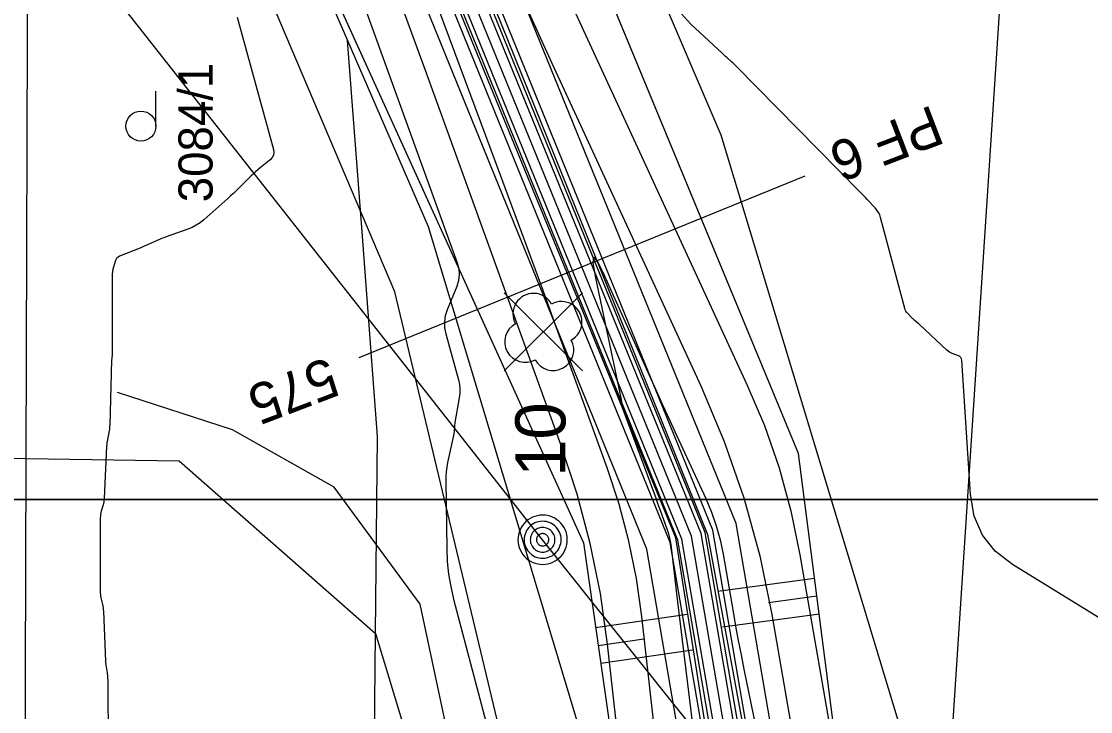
# Model space of a CAD drawing. Extents: x -534410 to -534262, y -1190162 to -1189584.
# Drawn here: x -534342.11 to -534315.47, y -1190009.76 to -1189992.55 of the extents above; entities that cross this region are included whole.
import ezdxf

# ---------------------------------------------------------------- set-up
doc = ezdxf.new("R2010")
doc.units = 0
for name, color, linetype in [('07_ELEKTRO', 7, 'Continuous'), ('30', 7, 'Continuous'), ('31', 7, 'Continuous'), ('_linie', 7, 'Continuous'), ('_N_osa', 7, 'Continuous'), ('_N_tenká', 7, 'Continuous'), ('_N_tenká_velmi', 7, 'Continuous'), ('_N_text', 7, 'Continuous'), ('_přístup', 7, 'Continuous'), ('_rámeček', 7, 'Continuous'), ('_tenka', 7, 'Continuous'), ('_velmi_tenka', 7, 'Continuous'), ('Default', 7, 'Continuous'), ('Hranice parcel', 7, 'Continuous'), ('Parcelní čísla', 7, 'Continuous'), ('Vrstva 12', 7, 'Continuous'), ('Vrstva 15', 7, 'Continuous'), ('Vrstva 2', 7, 'Continuous'), ('Značky kultur', 7, 'Continuous')]:
    doc.layers.add(name, color=color, linetype=linetype)

# ---------------------------------------------------------------- blocks, each defined once
blk = doc.blocks.new('VN460')
at = {"layer": 'Vrstva 2'}
for points in [[(0.1229, -0.0001), (0.1221, 0.0128), (0.1201, 0.0255), (0.1168, 0.0379), (0.1122, 0.0499), (0.1064, 0.0613), (0.0994, 0.0722), (0.0913, 0.0822), (0.0822, 0.0912), (0.0722, 0.0993), (0.0614, 0.1063), (0.05, 0.1122), (0.0379, 0.1168), (0.0256, 0.1201), (0.0128, 0.1221), (0, 0.1228), (-0.0128, 0.1221), (-0.0256, 0.1201), (-0.0379, 0.1168), (-0.05, 0.1122), (-0.0614, 0.1063), (-0.0722, 0.0993), (-0.0822, 0.0912), (-0.0913, 0.0822), (-0.0994, 0.0722), (-0.1064, 0.0613), (-0.1122, 0.0499), (-0.1168, 0.0379), (-0.1202, 0.0255), (-0.1221, 0.0128), (-0.1229, -0.0001), (-0.1221, -0.0129), (-0.1202, -0.0256), (-0.1168, -0.038), (-0.1122, -0.05), (-0.1064, -0.0615), (-0.0994, -0.0723), (-0.0913, -0.0823), (-0.0822, -0.0914), (-0.0722, -0.0995), (-0.0614, -0.1064), (-0.05, -0.1123), (-0.0379, -0.1169), (-0.0256, -0.1202), (-0.0128, -0.1223), (0, -0.1229), (0.0128, -0.1222), (0.0256, -0.1202), (0.0379, -0.1169), (0.05, -0.1123), (0.0614, -0.1064), (0.0722, -0.0995), (0.0822, -0.0914), (0.0913, -0.0823), (0.0994, -0.0723), (0.1064, -0.0615), (0.1122, -0.05), (0.1168, -0.038), (0.1201, -0.0256), (0.1221, -0.0129), (0.1229, -0.0001)], [(0.0922, -0.0001), (0.0916, 0.0096), (0.0901, 0.0191), (0.0876, 0.0284), (0.0842, 0.0374), (0.0798, 0.046), (0.0745, 0.0541), (0.0685, 0.0616), (0.0616, 0.0684), (0.0541, 0.0745), (0.046, 0.0797), (0.0375, 0.0841), (0.0285, 0.0876), (0.0191, 0.0901), (0.0096, 0.0916), (0, 0.0921), (-0.0096, 0.0916), (-0.0191, 0.0901), (-0.0285, 0.0876), (-0.0375, 0.0841), (-0.0461, 0.0797), (-0.0542, 0.0745), (-0.0617, 0.0684), (-0.0685, 0.0616), (-0.0745, 0.0541), (-0.0798, 0.046), (-0.0842, 0.0374), (-0.0876, 0.0284), (-0.0901, 0.0191), (-0.0916, 0.0096), (-0.0921, -0.0001), (-0.0916, -0.0097), (-0.0901, -0.0192), (-0.0876, -0.0285), (-0.0842, -0.0375), (-0.0798, -0.0461), (-0.0745, -0.0542), (-0.0685, -0.0617), (-0.0616, -0.0685), (-0.0542, -0.0746), (-0.0461, -0.0798), (-0.0375, -0.0842), (-0.0285, -0.0877), (-0.0191, -0.0902), (-0.0096, -0.0917), (0, -0.0922), (0.0096, -0.0917), (0.0191, -0.0902), (0.0285, -0.0877), (0.0375, -0.0842), (0.046, -0.0798), (0.0541, -0.0746), (0.0616, -0.0685), (0.0685, -0.0617), (0.0745, -0.0542), (0.0798, -0.0461), (0.0842, -0.0375), (0.0876, -0.0285), (0.0901, -0.0192), (0.0916, -0.0097), (0.0922, -0.0001)], [(0.0614, -0.0001), (0.0611, 0.0063), (0.0601, 0.0127), (0.0584, 0.0189), (0.0561, 0.0249), (0.0532, 0.0306), (0.0497, 0.036), (0.0456, 0.041), (0.0411, 0.0456), (0.0361, 0.0496), (0.0307, 0.0531), (0.025, 0.056), (0.019, 0.0584), (0.0128, 0.06), (0.0064, 0.061), (0, 0.0613), (-0.0064, 0.061), (-0.0128, 0.06), (-0.019, 0.0584), (-0.025, 0.056), (-0.0307, 0.0531), (-0.0361, 0.0496), (-0.0411, 0.0456), (-0.0457, 0.041), (-0.0497, 0.036), (-0.0532, 0.0306), (-0.0561, 0.0249), (-0.0584, 0.0189), (-0.0601, 0.0127), (-0.0611, 0.0063), (-0.0614, -0.0001), (-0.0611, -0.0065), (-0.0601, -0.0128), (-0.0584, -0.0191), (-0.0561, -0.025), (-0.0532, -0.0308), (-0.0497, -0.0361), (-0.0457, -0.0411), (-0.0411, -0.0457), (-0.0361, -0.0498), (-0.0307, -0.0532), (-0.025, -0.0561), (-0.019, -0.0585), (-0.0128, -0.0601), (-0.0064, -0.0611), (0, -0.0615), (0.0064, -0.0611), (0.0128, -0.0601), (0.019, -0.0585), (0.025, -0.0561), (0.0307, -0.0532), (0.0361, -0.0498), (0.0411, -0.0457), (0.0456, -0.0411), (0.0497, -0.0361), (0.0532, -0.0308), (0.0561, -0.025), (0.0584, -0.0191), (0.0601, -0.0128), (0.0611, -0.0065), (0.0614, -0.0001)], [(0.0307, -0.0001), (0.0306, 0.0031), (0.03, 0.0063), (0.0292, 0.0094), (0.0281, 0.0124), (0.0266, 0.0153), (0.0248, 0.018), (0.0228, 0.0205), (0.0206, 0.0228), (0.0181, 0.0248), (0.0153, 0.0265), (0.0125, 0.028), (0.0095, 0.0291), (0.0064, 0.03), (0.0032, 0.0305), (0, 0.0306), (-0.0032, 0.0305), (-0.0064, 0.03), (-0.0095, 0.0291), (-0.0125, 0.028), (-0.0154, 0.0265), (-0.0181, 0.0248), (-0.0206, 0.0228), (-0.0228, 0.0205), (-0.0248, 0.018), (-0.0266, 0.0153), (-0.0281, 0.0124), (-0.0292, 0.0094), (-0.03, 0.0063), (-0.0306, 0.0031), (-0.0307, -0.0001), (-0.0306, -0.0033), (-0.03, -0.0065), (-0.0292, -0.0095), (-0.0281, -0.0126), (-0.0266, -0.0154), (-0.0248, -0.0181), (-0.0228, -0.0206), (-0.0206, -0.0229), (-0.0181, -0.0249), (-0.0154, -0.0267), (-0.0125, -0.0281), (-0.0095, -0.0292), (-0.0064, -0.0301), (-0.0032, -0.0306), (0, -0.0308), (0.0032, -0.0306), (0.0064, -0.0301), (0.0095, -0.0292), (0.0125, -0.0281), (0.0153, -0.0267), (0.0181, -0.0249), (0.0206, -0.0229), (0.0228, -0.0206), (0.0248, -0.0181), (0.0266, -0.0154), (0.0281, -0.0126), (0.0292, -0.0095), (0.03, -0.0065), (0.0306, -0.0033), (0.0307, -0.0001)]]:
    blk.add_lwpolyline(points, dxfattribs=at)

msp = doc.modelspace()

# ---------------------------------------------------------------- linework, layer by layer
at = {"layer": '07_ELEKTRO'}
msp.add_lwpolyline([(-534329.31, -1190087.46), (-534329.03, -1190079.95), (-534329.01, -1190078.66), (-534328.95, -1190069.47), (-534328.91, -1190061.75), (-534328.68, -1190054.09), (-534328.55, -1190046.44), (-534328.261, -1190025.497), (-534332.174, -1190007.081), (-534334.321, -1190004.167), (-534336.852, -1190002.737), (-534339.713, -1190001.803)], dxfattribs=at)
at = {"layer": '30'}
for points in [[(-534330.583, -1189987.403), (-534324.037, -1190001.603), (-534323.602, -1190002.632), (-534323.237, -1190003.683), (-534322.942, -1190004.756), (-534322.716, -1190005.85), (-534321.8, -1190011.157)], [(-534326.785, -1190014.533), (-534327.509, -1190008.078), (-534327.688, -1190006.814), (-534327.941, -1190005.568), (-534328.266, -1190004.338), (-534328.664, -1190003.126), (-534331.461, -1189995.381), (-534332.074, -1189993.689), (-534332.691, -1189991.999)], [(-534336.734, -1189992.452), (-534335.832, -1189995.749), (-534335.821, -1189995.823), (-534335.831, -1189995.889), (-534335.862, -1189995.95), (-534335.913, -1189996.003), (-534336.159, -1189996.205), (-534336.22, -1189996.256), (-534336.279, -1189996.308), (-534336.338, -1189996.362), (-534336.395, -1189996.417), (-534336.69, -1189996.71), (-534336.759, -1189996.777), (-534336.828, -1189996.843), (-534336.898, -1189996.907), (-534336.97, -1189996.971), (-534337.569, -1189997.502), (-534337.659, -1189997.574), (-534337.754, -1189997.637), (-534337.855, -1189997.69), (-534337.962, -1189997.734), (-534338.503, -1189997.928), (-534338.56, -1189997.949), (-534338.617, -1189997.971), (-534338.674, -1189997.995), (-534338.73, -1189998.019), (-534338.954, -1189998.118), (-534339.01, -1189998.142), (-534339.066, -1189998.166), (-534339.122, -1189998.19), (-534339.179, -1189998.213), (-534339.668, -1189998.411), (-534339.702, -1189998.429), (-534339.73, -1189998.453), (-534339.751, -1189998.483), (-534339.766, -1189998.519), (-534339.829, -1189998.73), (-534339.832, -1189998.741), (-534339.835, -1189998.752), (-534339.837, -1189998.764), (-534339.839, -1189998.775), (-534339.845, -1189998.821), (-534339.846, -1189998.833), (-534339.847, -1189998.845), (-534339.848, -1189998.856), (-534339.848, -1189998.868), (-534339.848, -1190000.815), (-534339.848, -1190000.83), (-534339.849, -1190000.844), (-534339.85, -1190000.859), (-534339.851, -1190000.874), (-534339.858, -1190000.934), (-534339.86, -1190000.948), (-534339.861, -1190000.963), (-534339.862, -1190000.978), (-534339.863, -1190000.993), (-534339.912, -1190002.632), (-534339.913, -1190002.653), (-534339.914, -1190002.674), (-534339.916, -1190002.696), (-534339.919, -1190002.717), (-534339.932, -1190002.802), (-534339.935, -1190002.823), (-534339.938, -1190002.844), (-534339.942, -1190002.866), (-534339.946, -1190002.887), (-534339.973, -1190003.026), (-534339.979, -1190003.056), (-534339.983, -1190003.087), (-534339.986, -1190003.118), (-534339.988, -1190003.148), (-534340.052, -1190004.45), (-534340.055, -1190004.491), (-534340.06, -1190004.531), (-534340.068, -1190004.571), (-534340.078, -1190004.61), (-534340.123, -1190004.766), (-534340.132, -1190004.806), (-534340.139, -1190004.845), (-534340.144, -1190004.885), (-534340.145, -1190004.926), (-534340.147, -1190005.148), (-534340.147, -1190005.198), (-534340.147, -1190005.249), (-534340.147, -1190005.299), (-534340.147, -1190005.35), (-534340.147, -1190006.339), (-534340.147, -1190006.39), (-534340.147, -1190006.44), (-534340.148, -1190006.491), (-534340.148, -1190006.541), (-534340.149, -1190006.76), (-534340.148, -1190006.802), (-534340.144, -1190006.844), (-534340.138, -1190006.885), (-534340.13, -1190006.926), (-534340.09, -1190007.09), (-534340.081, -1190007.131), (-534340.074, -1190007.172), (-534340.07, -1190007.214), (-534340.067, -1190007.256), (-534340.016, -1190008.506), (-534340.014, -1190008.541), (-534340.011, -1190008.575), (-534340.006, -1190008.608), (-534340.001, -1190008.642), (-534339.975, -1190008.792), (-534339.971, -1190008.818), (-534339.967, -1190008.845), (-534339.965, -1190008.871), (-534339.964, -1190008.898), (-534339.96, -1190009.005), (-534339.959, -1190009.032), (-534339.958, -1190009.059), (-534339.958, -1190009.086), (-534339.957, -1190009.113), (-534339.946, -1190010.519)], [(-534324.401, -1190018.116), (-534325.773, -1190006.894), (-534325.791, -1190006.749), (-534325.808, -1190006.603), (-534325.825, -1190006.457), (-534325.842, -1190006.312), (-534325.914, -1190005.671), (-534325.93, -1190005.555), (-534325.953, -1190005.44), (-534325.983, -1190005.327), (-534326.02, -1190005.215), (-534326.18, -1190004.773), (-534326.22, -1190004.662), (-534326.26, -1190004.551), (-534326.301, -1190004.441), (-534326.342, -1190004.331), (-534327.097, -1190002.3), (-534327.11, -1190002.262), (-534327.121, -1190002.223), (-534327.13, -1190002.184), (-534327.138, -1190002.144), (-534327.164, -1190001.983), (-534327.171, -1190001.943), (-534327.178, -1190001.903), (-534327.186, -1190001.863), (-534327.194, -1190001.823), (-534327.798, -1189998.945), (-534327.863, -1189998.571), (-534327.85, -1189998.436), (-534327.76, -1189998.538), (-534327.592, -1189998.878), (-534326.468, -1190001.378), (-534326.299, -1190001.753), (-534326.13, -1190002.127), (-534325.959, -1190002.501), (-534325.787, -1190002.874), (-534325.06, -1190004.451), (-534324.919, -1190004.786), (-534324.8, -1190005.128), (-534324.704, -1190005.477), (-534324.631, -1190005.833), (-534324.382, -1190007.272), (-534324.319, -1190007.631), (-534324.253, -1190007.99), (-534324.183, -1190008.348), (-534324.111, -1190008.706), (-534322.204, -1190017.993)]]:
    msp.add_lwpolyline(points, dxfattribs=at)
at = {"layer": '31'}
for points in [[(-534325.036, -1190022.469), (-534325.055, -1190021.635), (-534325.106, -1190020.801), (-534325.192, -1190019.969), (-534325.598, -1190016.645), (-534325.699, -1190015.814), (-534325.797, -1190014.982), (-534325.894, -1190014.15), (-534325.988, -1190013.318), (-534326.654, -1190007.39), (-534326.788, -1190006.444), (-534326.977, -1190005.511), (-534327.22, -1190004.59), (-534327.518, -1190003.682), (-534328.82, -1190000.077), (-534329.147, -1189999.176), (-534329.476, -1189998.275), (-534329.807, -1189997.376), (-534330.139, -1189996.477), (-534336.286, -1189979.943)], [(-534334.815, -1189980.466), (-534330.995, -1189988.966), (-534330.298, -1189990.512), (-534329.597, -1189992.056), (-534328.893, -1189993.598), (-534328.185, -1189995.139), (-534325.187, -1190001.643), (-534324.603, -1190003.024), (-534324.113, -1190004.435), (-534323.717, -1190005.875), (-534323.414, -1190007.344), (-534322.095, -1190014.986), (-534321.984, -1190015.614), (-534321.868, -1190016.242), (-534321.747, -1190016.868), (-534321.621, -1190017.494), (-534321.51, -1190018.033)], [(-534334.708, -1189989.006), (-534331.253, -1189998.572), (-534331.214, -1189998.72), (-534331.203, -1189998.868), (-534331.22, -1189999.015), (-534331.265, -1189999.161), (-534331.503, -1189999.746), (-534331.55, -1189999.893), (-534331.571, -1190000.041), (-534331.568, -1190000.191), (-534331.539, -1190000.342), (-534331.224, -1190001.494), (-534331.2, -1190001.605), (-534331.188, -1190001.715), (-534331.189, -1190001.827), (-534331.203, -1190001.939), (-534331.31, -1190002.554), (-534331.314, -1190002.583), (-534331.318, -1190002.613), (-534331.322, -1190002.642), (-534331.324, -1190002.672), (-534331.337, -1190002.845), (-534331.338, -1190002.851), (-534331.339, -1190002.856), (-534331.345, -1190002.87), (-534331.347, -1190002.876), (-534331.347, -1190002.879), (-534331.494, -1190003.555), (-534331.516, -1190003.669), (-534331.53, -1190003.784), (-534331.539, -1190003.899), (-534331.54, -1190004.015), (-534331.516, -1190005.699), (-534331.502, -1190006.017), (-534331.469, -1190006.332), (-534331.416, -1190006.645), (-534331.344, -1190006.955), (-534330.495, -1190010.169)], [(-534311.946, -1190009.465), (-534317.42, -1190006.098), (-534317.852, -1190005.764), (-534318.17, -1190005.362), (-534318.376, -1190004.892), (-534318.47, -1190004.353), (-534318.684, -1190001.002), (-534318.691, -1190000.965), (-534318.707, -1190000.934), (-534318.732, -1190000.91), (-534318.766, -1190000.893), (-534318.919, -1190000.837), (-534318.956, -1190000.821), (-534318.991, -1190000.802), (-534319.024, -1190000.779), (-534319.055, -1190000.753), (-534319.731, -1190000.119), (-534319.74, -1190000.111), (-534319.748, -1190000.104), (-534319.757, -1190000.096), (-534319.766, -1190000.088), (-534319.836, -1190000.029), (-534319.88, -1189999.991), (-534319.89, -1189999.982), (-534319.9, -1189999.973), (-534319.91, -1189999.964), (-534319.919, -1189999.954), (-534320.038, -1189999.829), (-534320.06, -1189999.804), (-534320.077, -1189999.776), (-534320.091, -1189999.747), (-534320.102, -1189999.716), (-534320.707, -1189997.445), (-534320.729, -1189997.378), (-534320.759, -1189997.316), (-534320.796, -1189997.257), (-534320.841, -1189997.204), (-534321.037, -1189996.997), (-534321.086, -1189996.946), (-534321.136, -1189996.894), (-534321.185, -1189996.843), (-534321.235, -1189996.792), (-534324.301, -1189993.675), (-534324.329, -1189993.646), (-534324.358, -1189993.619), (-534324.387, -1189993.591), (-534324.417, -1189993.564), (-534324.536, -1189993.456), (-534324.566, -1189993.429), (-534324.595, -1189993.402), (-534324.625, -1189993.375), (-534324.654, -1189993.348), (-534325.431, -1189992.628), (-534325.433, -1189992.626), (-534327.845, -1189989.955)]]:
    msp.add_lwpolyline(points, dxfattribs=at)
at = {"layer": '_linie'}
for points in [[(-534351.8, -1189951.99), (-534346.88, -1189964.25), (-534328.11, -1190005.55), (-534325.796, -1190021.686), (-534325.86, -1190050.97), (-534326.22, -1190078.56), (-534326.79, -1190120.4), (-534329.12, -1190134.93), (-534323.49, -1190133.89), (-534321.38, -1190121.46), (-534319.59, -1190053.22), (-534320.45, -1190021.195), (-534322.75, -1190003.33), (-534340.65, -1189960.04), (-534344.52, -1189948.89)], [(-534347.45, -1189950.137), (-534345.54, -1189954.54), (-534325.02, -1190005.35), (-534322.054, -1190021.393), (-534321.72, -1190051.56), (-534322.31, -1190078.15), (-534323.81, -1190120.37), (-534326.521, -1190134.45)], [(-534328.194, -1190134.759), (-534324.85, -1190120.45), (-534324.6, -1190078.17), (-534323.54, -1190051.92), (-534323.273, -1190021.516), (-534325.81, -1190005.43), (-534346.66, -1189954.59), (-534348.342, -1189950.518)]]:
    msp.add_lwpolyline(points, dxfattribs=at)
at = {"layer": '_N_osa'}
msp.add_lwpolyline([(-534327.357, -1190134.604), (-534324.33, -1190120.41), (-534323.455, -1190078.16), (-534322.63, -1190051.74), (-534322.663, -1190021.455), (-534325.415, -1190005.39), (-534346.1, -1189954.565), (-534347.892, -1189950.326)], dxfattribs=at)
at = {"layer": '_N_tenká'}
for points in [[(-534326.133, -1190134.378), (-534323.183, -1190120.543), (-534322.305, -1190078.19), (-534321.48, -1190051.757), (-534321.513, -1190021.356), (-534324.303, -1190005.072), (-534345.038, -1189954.124), (-534346.832, -1189949.878)], [(-534328.581, -1190134.83), (-534325.477, -1190120.277), (-534324.605, -1190078.13), (-534323.78, -1190051.723), (-534323.813, -1190021.553), (-534326.527, -1190005.708), (-534347.162, -1189955.006), (-534348.951, -1189950.773)]]:
    msp.add_lwpolyline(points, dxfattribs=at)
at = {"layer": '_N_tenká_velmi'}
for points in [[(-534327.091, -1190134.555), (-534324.081, -1190120.439), (-534323.205, -1190078.166), (-534322.38, -1190051.744), (-534322.413, -1190021.433), (-534325.173, -1190005.321), (-534345.869, -1189954.469), (-534347.661, -1189950.228)], [(-534326.985, -1190134.536), (-534323.981, -1190120.45), (-534323.105, -1190078.169), (-534322.28, -1190051.745), (-534322.313, -1190021.425), (-534325.076, -1190005.293), (-534345.777, -1189954.431), (-534347.569, -1189950.189)], [(-534326.772, -1190134.496), (-534323.781, -1190120.474), (-534322.905, -1190078.174), (-534322.08, -1190051.748), (-534322.113, -1190021.407), (-534324.883, -1190005.238), (-534345.592, -1189954.354), (-534347.385, -1189950.112)], [(-534327.943, -1190134.713), (-534324.879, -1190120.346), (-534324.005, -1190078.146), (-534323.18, -1190051.732), (-534323.213, -1190021.502), (-534325.947, -1190005.542), (-534346.608, -1189954.776), (-534348.398, -1189950.54)], [(-534327.73, -1190134.673), (-534324.679, -1190120.37), (-534323.805, -1190078.151), (-534322.98, -1190051.735), (-534323.013, -1190021.485), (-534325.754, -1190005.487), (-534346.423, -1189954.699), (-534348.214, -1189950.462)], [(-534327.623, -1190134.654), (-534324.579, -1190120.381), (-534323.705, -1190078.154), (-534322.88, -1190051.736), (-534322.913, -1190021.476), (-534325.657, -1190005.459), (-534346.331, -1189954.661), (-534348.122, -1189950.423)]]:
    msp.add_lwpolyline(points, dxfattribs=at)
at = {"layer": '_N_text'}
msp.add_lwpolyline([(-534322.59, -1189996.415), (-534333.705, -1190000.939)], dxfattribs=at)
at = {"layer": '_přístup'}
for p, q in [((-534328.134, -1190001.269), (-534330.081, -1189999.323)), ((-534330.081, -1190001.269), (-534328.134, -1189999.323))]:
    msp.add_line(p, q, dxfattribs=at)
msp.add_lwpolyline([(-534330.552, -1190135.191), (-534328.648, -1190119.819), (-534326.845, -1190024.247), (-534332.805, -1189999.297), (-534354.454, -1189948.317)], dxfattribs=at)
msp.add_circle((-534329.108, -1190000.296), 0.000512, dxfattribs=at)
for centre, start, end in [((-534329.353, -1189999.847), 28.6209, 208.6209), ((-534328.658, -1190000.051), 298.6209, 118.6209), ((-534329.557, -1190000.541), 118.6209, 298.6209), ((-534328.862, -1190000.746), 208.6209, 28.6209)]:
    msp.add_arc(centre, 0.512, start, end, dxfattribs=at)
at = {"layer": '_rámeček'}
for points in [[(-534410.126, -1189899.47), (-534261.626, -1189899.47), (-534261.626, -1190004.47), (-534410.126, -1190004.47)], [(-534410.126, -1190004.47), (-534261.626, -1190004.47), (-534261.626, -1190109.47), (-534410.126, -1190109.47)]]:
    msp.add_lwpolyline(points, close=True, dxfattribs=at)
at = {"layer": '_tenka'}
for points in [[(-534351.8, -1189951.99), (-534346.88, -1189964.25), (-534328.11, -1190005.55), (-534325.796, -1190021.686), (-534325.86, -1190050.97), (-534326.22, -1190078.56), (-534326.79, -1190120.4), (-534329.12, -1190134.93), (-534323.49, -1190133.89), (-534321.38, -1190121.46), (-534319.59, -1190053.22), (-534320.45, -1190021.195), (-534322.75, -1190003.33), (-534340.65, -1189960.04), (-534344.52, -1189948.89)], [(-534327.55, -1190134.64), (-534323.49, -1190133.89), (-534321.38, -1190121.46), (-534319.59, -1190053.22), (-534320.45, -1190021.195), (-534322.75, -1190003.33), (-534340.65, -1189960.04), (-534344.52, -1189948.89)], [(-534347.45, -1189950.137), (-534345.54, -1189954.54), (-534325.02, -1190005.35), (-534322.054, -1190021.393), (-534321.72, -1190051.56), (-534322.31, -1190078.15), (-534323.81, -1190120.37), (-534326.521, -1190134.45)], [(-534347.45, -1189950.137), (-534345.54, -1189954.54), (-534325.02, -1190005.35), (-534322.054, -1190021.393), (-534321.72, -1190051.56), (-534322.31, -1190078.15), (-534323.81, -1190120.37), (-534326.521, -1190134.45)], [(-534328.194, -1190134.759), (-534324.85, -1190120.45), (-534324.6, -1190078.17), (-534323.54, -1190051.92), (-534323.273, -1190021.516), (-534325.81, -1190005.43), (-534346.66, -1189954.59), (-534348.342, -1189950.518)], [(-534328.194, -1190134.759), (-534324.85, -1190120.45), (-534324.6, -1190078.17), (-534323.54, -1190051.92), (-534323.273, -1190021.516), (-534325.81, -1190005.43), (-534346.66, -1189954.59), (-534348.342, -1189950.518)], [(-534351.8, -1189951.99), (-534346.88, -1189964.25), (-534328.11, -1190005.55), (-534325.796, -1190021.686), (-534325.86, -1190050.97), (-534326.22, -1190078.56), (-534326.79, -1190120.4), (-534329.12, -1190134.93), (-534327.55, -1190134.64)]]:
    msp.add_lwpolyline(points, dxfattribs=at)
at = {"layer": '_velmi_tenka'}
for p, q in [((-534322.352, -1190006.44), (-534324.763, -1190006.763)), ((-534322.292, -1190006.886), (-534323.497, -1190007.047)), ((-534327.807, -1190007.664), (-534325.526, -1190007.333)), ((-534322.232, -1190007.332), (-534324.643, -1190007.655)), ((-534327.743, -1190008.11), (-534326.602, -1190007.944)), ((-534327.678, -1190008.555), (-534325.396, -1190008.224))]:
    msp.add_line(p, q, dxfattribs=at)
at = {"layer": 'Default'}
for p, q in [((-534322.75, -1190003.33), (-534340.65, -1189960.04)), ((-534346.88, -1189964.25), (-534328.11, -1190005.55))]:
    msp.add_line(p, q, dxfattribs=at)
for points in [[(-534319.59, -1190053.22), (-534320.45, -1190021.195), (-534322.75, -1190003.33)], [(-534328.11, -1190005.55), (-534325.796, -1190021.686), (-534325.86, -1190050.97)]]:
    msp.add_lwpolyline(points, dxfattribs=at)
at = {"layer": 'Hranice parcel'}
for p, q in [((-534319.25, -1190015.38), (-534314.72, -1189945.99)), ((-534341.9, -1189974.75), (-534333.99, -1189993.03)), ((-534365.84, -1190003.05), (-534341.99, -1190003.45)), ((-534333.46, -1190024.63), (-534333.29, -1190007.81)), ((-534333.29, -1190007.81), (-534328.17, -1190024.72))]:
    msp.add_line(p, q, dxfattribs=at)
for points in [[(-534341.99, -1190003.45), (-534341.91, -1189977.12), (-534341.9, -1189974.75)], [(-534319.25, -1190015.38), (-534319.67, -1190011.96), (-534324.68, -1189995.39), (-534326.36, -1189991.44)], [(-534333.29, -1190007.81), (-534333.24, -1190002.9), (-534333.62, -1189997.8), (-534333.99, -1189993.03)], [(-534333.99, -1189993.03), (-534331.98, -1189997.67), (-534327.34, -1190013.08), (-534325.48, -1190021.81), (-534326.93, -1190073), (-534328.13, -1190128.3), (-534328.71, -1190131.86)], [(-534342.06, -1190024.47), (-534342.05, -1190022.37), (-534341.99, -1190003.45)], [(-534341.99, -1190003.45), (-534338.18, -1190003.51), (-534333.29, -1190007.81)]]:
    msp.add_lwpolyline(points, dxfattribs=at)
at = {"layer": 'Vrstva 12'}
msp.add_lwpolyline([(-534315.834, -1190022.126), (-534329.125, -1190005.478), (-534340.302, -1189991.272)], dxfattribs=at)
at = {"layer": 'Značky kultur'}
msp.add_line((-534338.758, -1189995.166), (-534338.758, -1189994.291), dxfattribs=at)
msp.add_circle((-534339.134, -1189995.166), 0.375, dxfattribs=at)

# ---------------------------------------------------------------- block references
at = {"layer": 'Vrstva 15', "xscale": 5.000000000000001, "yscale": 5.000000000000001, "rotation": -53.49649728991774}
msp.add_blockref('VN460', (-534329.125, -1190005.477), dxfattribs=at)

# ---------------------------------------------------------------- texts
at = {"layer": '_N_text'}
for s, rotation, p in [('PF 6', 200.9666, (-534319.416, -1189994.63)), ('575', 200.9191, (-534334.468, -1190000.907))]:
    msp.add_text(s, height=1, rotation=rotation, dxfattribs=at).set_placement(p)
at = {"layer": '_přístup'}
msp.add_text('10', height=1.25, rotation=90, dxfattribs=at).set_placement((-534328.557, -1190003.909))
at = {"layer": 'Parcelní čísla'}
msp.add_text('3084/1', height=0.85, rotation=90, dxfattribs=at).set_placement((-534337.348, -1189997.063))

doc.saveas('drawing.dxf')
